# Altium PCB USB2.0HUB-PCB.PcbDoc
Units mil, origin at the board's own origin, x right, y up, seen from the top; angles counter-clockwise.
Board outline 1475 x 1955 mil, 2 copper layers (Top Layer, Bottom Layer); 18 components, 17 nets, 70 pads, 63 vias.
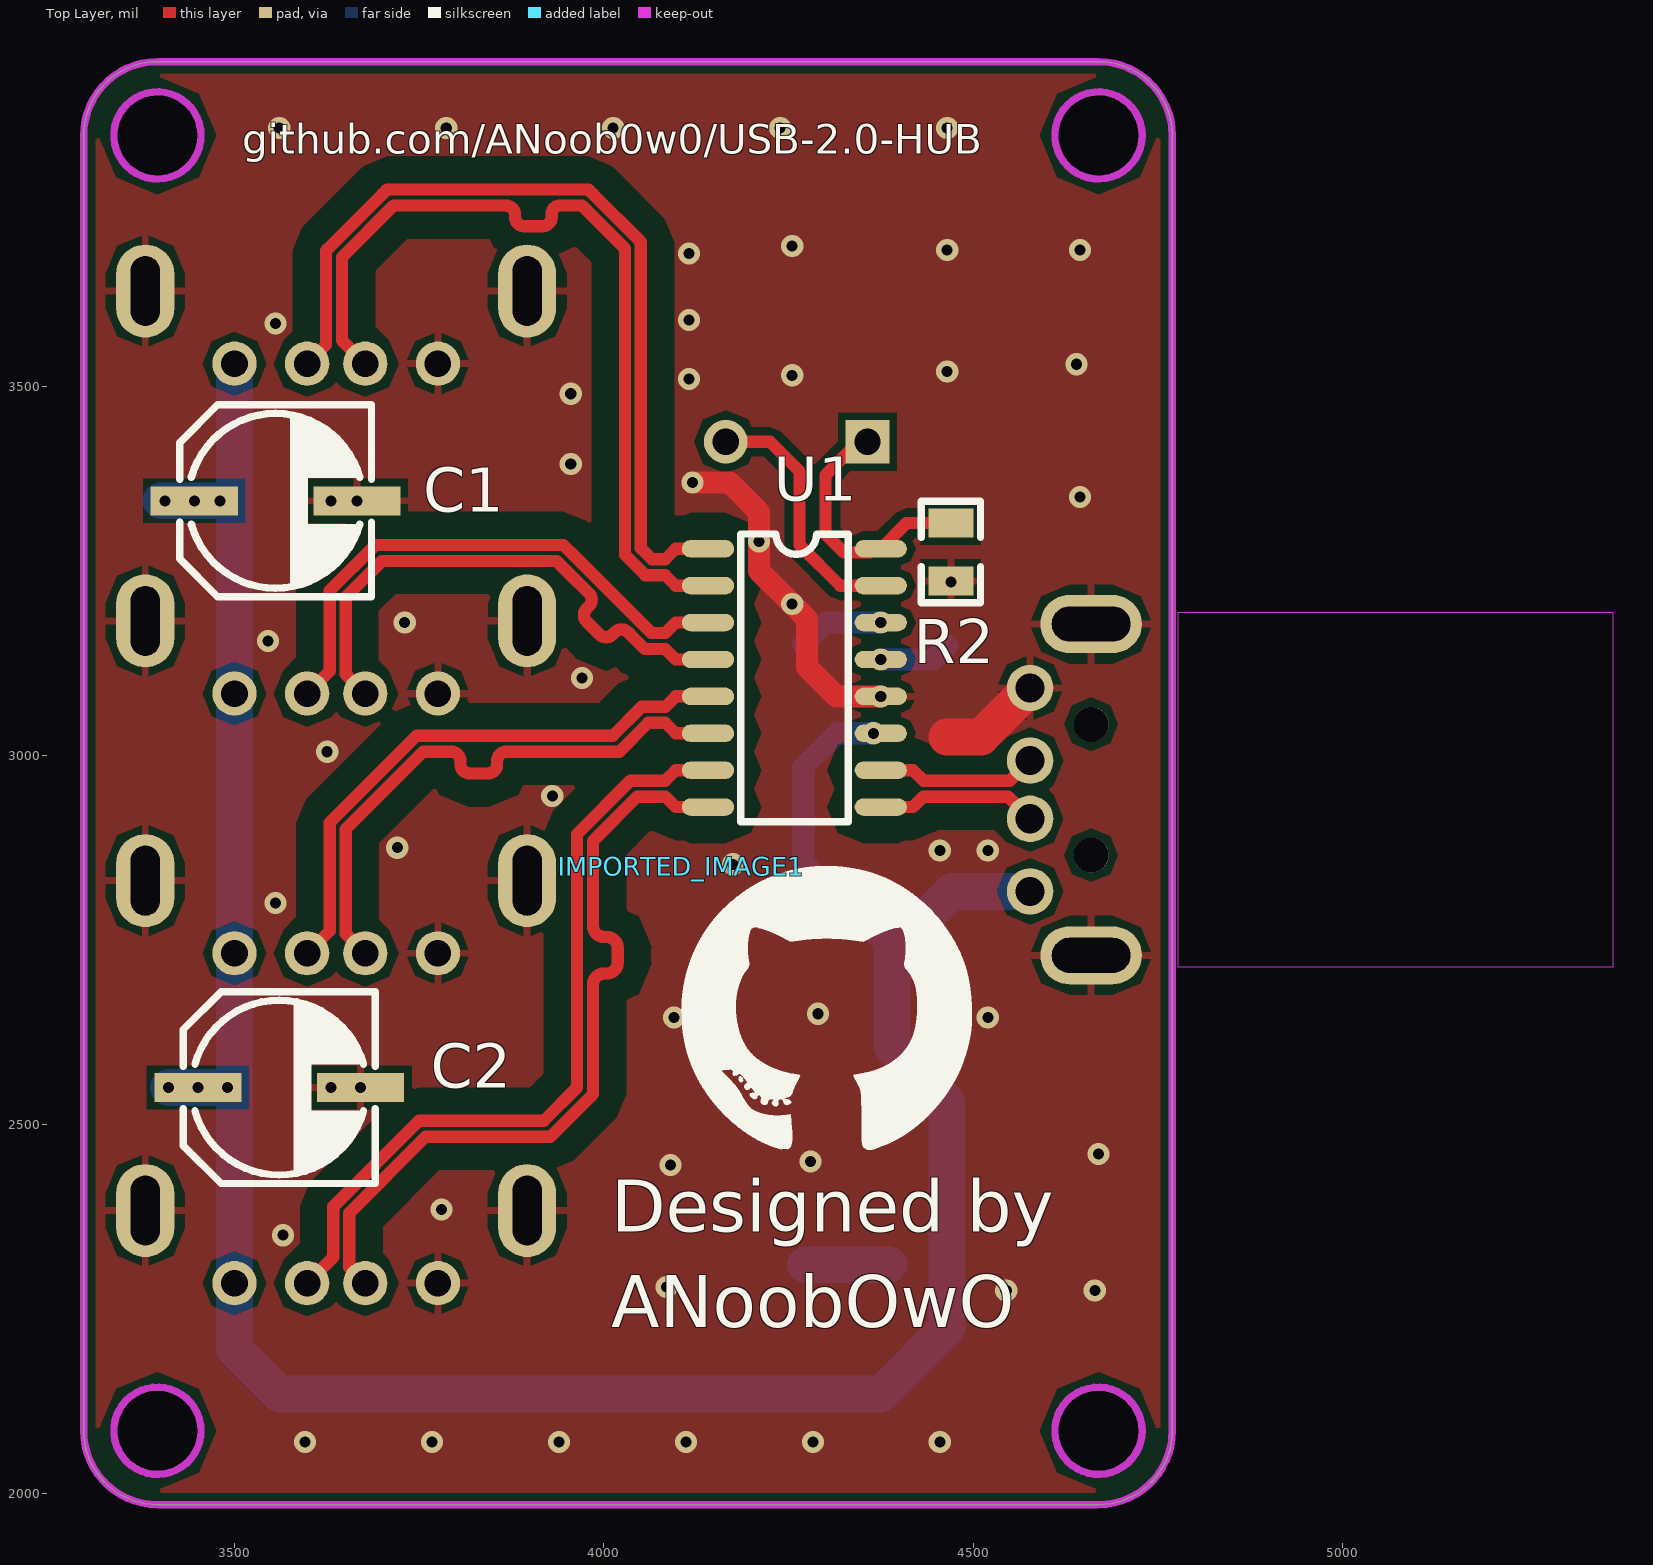
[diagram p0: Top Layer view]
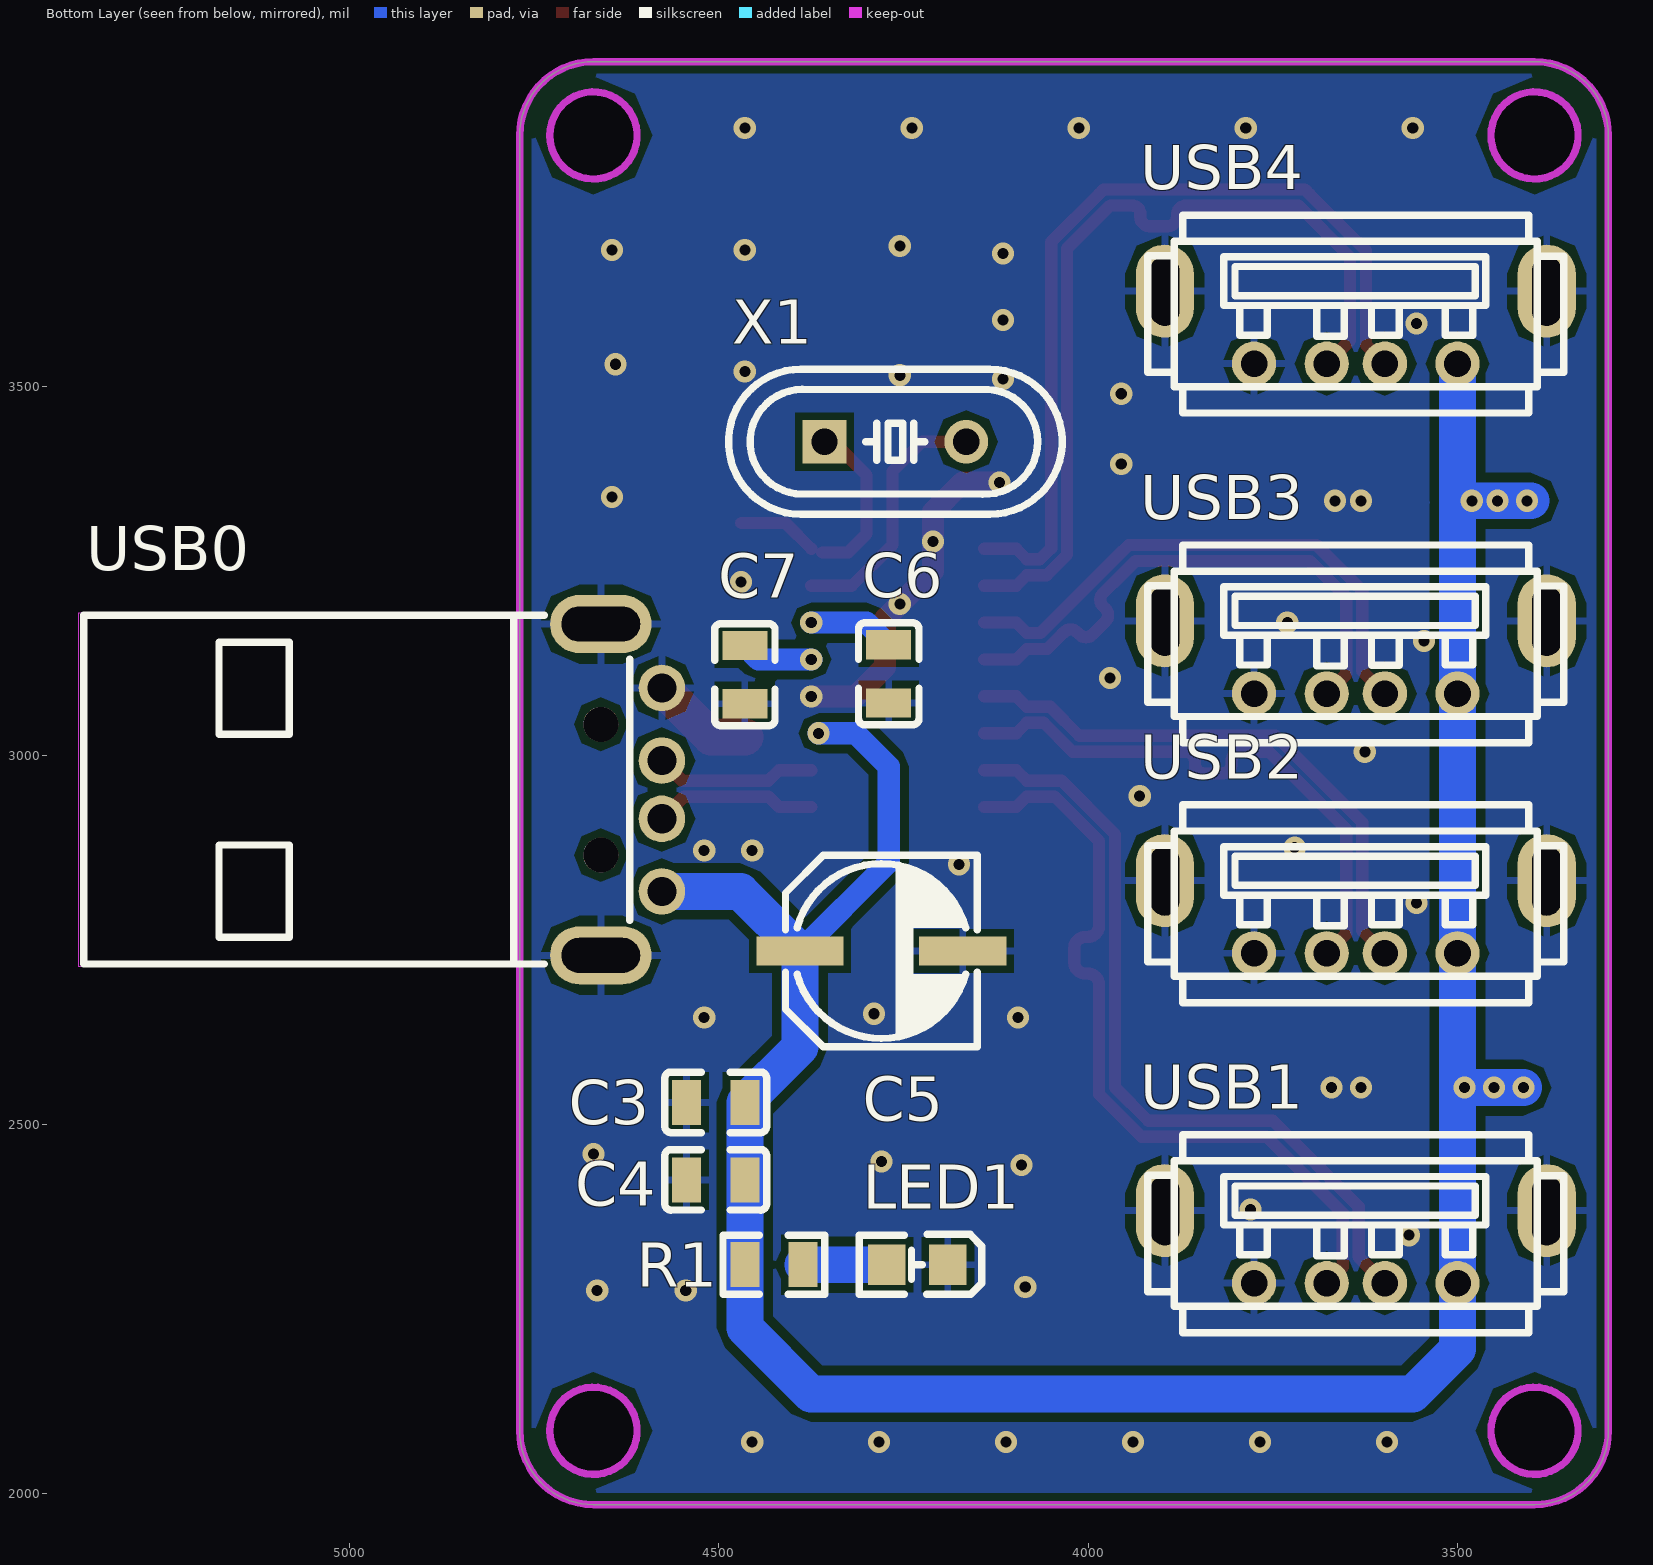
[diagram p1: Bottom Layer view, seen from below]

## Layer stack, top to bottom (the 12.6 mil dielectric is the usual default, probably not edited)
Top Solder: solder mask 0.4, Solder Resist, Dk 3.5
Top Layer: signal copper 1.4
Dielectric 1: dielectric 12.6, FR-4, Dk 4.8
Bottom Layer: signal copper 1.4
Bottom Solder: solder mask 0.4, Solder Resist, Dk 3.5

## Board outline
3295,2085 ccw(c3395,2085) 3395,1985 4670,1985 ccw(c4670,2085) 4770,2085 4770,3840 ccw(c4670,3840) 4670,3940 3395,3940 ccw(c3395,3840) 3295,3840
cut-out: 4610.94,3840 ccw(c4670,3840) 4670,3780.94 ccw(c4670,3840) 4729.06,3840 ccw(c4670,3840) 4670,3899.06 ccw(c4670,3840)
cut-out: 4610.94,2085 ccw(c4670,2085) 4670,2025.94 ccw(c4670,2085) 4729.06,2085 ccw(c4670,2085) 4670,2144.06 ccw(c4670,2085)
cut-out: 3335.94,2085 cw(c3395,2085) 3395,2144.06 cw(c3395,2085) 3454.06,2085 cw(c3395,2085) 3395,2025.94 cw(c3395,2085)
cut-out: 3395,3780.94 cw(c3395,3840) 3335.94,3840 cw(c3395,3840) 3395,3899.06 cw(c3395,3840) 3454.06,3840 cw(c3395,3840)
cut-out: 3450,3855

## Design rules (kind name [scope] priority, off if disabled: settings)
Clearance Clearance_polygon_top [InPolygon vs InNetClass('signal')  And OnTopLayer] p1: gap=33.28 ignorepadtopadclearanceinfootprint=FALSE
Clearance Clearance_polygon [InPolygon] p2: gap=10 ignorepadtopadclearanceinfootprint=FALSE
Clearance [All] p3: gap=5 ignorepadtopadclearanceinfootprint=FALSE
DiffPairsRouting [All] p1: maxlimit=10 minlimit=5 mostfreqgap=5 toplayer_minwidth=10 toplayer_maxwidth=20 toplayer_prefwidth=16.64 bottomlayer_minwidth=10 bottomlayer_maxwidth=20 bottomlayer_prefwidth=16.64 maxuncoupledlength=500
PlaneClearance [All] p1 off: clearance=20
PlaneConnect PlaneConnect_Via [IsVia] p1: planeconnectstyle=Direct reliefexpansion=20 reliefentries=4 reliefconductorwidth=10 reliefairgap=10
PlaneConnect [All] p2: pad.planeconnectstyle=Relief pad.reliefexpansion=20 pad.reliefentries=4 pad.reliefconductorwidth=10 pad.reliefairgap=10 via.planeconnectstyle=Direct via.reliefexpansion=20 via.reliefentries=4 via.reliefconductorwidth=10 via.reliefairgap=10
PolygonConnect PolygonConnect_Via [IsVia] p1: connectstyle=Direct reliefconductorwidth=10 reliefentries=4 polygonreliefangle="90 Angle" airgapwidth=10
PolygonConnect [All] p2: thpad.connectstyle=Relief thpad.reliefconductorwidth=10 thpad.reliefentries=4 thpad.polygonreliefangle="90 Angle" thpad.airgapwidth=10 smdpad.connectstyle=Relief smdpad.reliefconductorwidth=10 smdpad.reliefentries=4 smdpad.polygonreliefangle="90 Angle" smdpad.airgapwidth=10 via.connectstyle=Direct via.reliefconductorwidth=10 via.reliefentries=4 via.polygonreliefangle="90 Angle" via.airgapwidth=10
RoutingVias [All] p1: holewidth=15 width=30 viastyle="Through Hole" minholewidth=12.5 minwidth=25 maxholewidth=28 maxwidth=50
SolderMaskExpansion [All] p1: expansion=4
Width [All] p1: maxlimit=50 minlimit=10 preferedwidth=16.64 minimp=50.000000 maximp=50.000000 favimp=50.000000
27 further rules are at their usual default settings.

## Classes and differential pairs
net class signal: NetU1_1 NetU1_2 NetU1_3 NetU1_4 NetU1_5 NetU1_6 NetU1_7 NetU1_8 NetU1_9 NetU1_10
differential pair class "USB 90OM": NewDifferentialPair1 NewDifferentialPair2 NewDifferentialPair3 NewDifferentialPair4 NewDifferentialPair5
component class USB2.0HUB: C1 C2 C3 C4 C5 C6 C7 LED1 R1 R2 U1 USB0 USB1 USB2 USB3 USB4 X1
differential pair NewDifferentialPair5: +NetU1_10 -NetU1_9
differential pair NewDifferentialPair4: +NetU1_8 -NetU1_7
differential pair NewDifferentialPair3: +NetU1_6 -NetU1_5
differential pair NewDifferentialPair2: +NetU1_4 -NetU1_3
differential pair NewDifferentialPair1: +NetU1_2 -NetU1_1

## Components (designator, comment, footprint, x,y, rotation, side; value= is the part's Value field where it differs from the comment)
C1 "220uF" CAP-SMD_BD6.3-L6.6-W6.6-FD 3555,3345 r0 top
C2 "220uF" CAP-SMD_BD6.3-L6.6-W6.6-FD 3560,2550 r0 top
C3 "1uF" C0805 4504.37,2530 r180 bottom
C4 "10nF" C0805 4504.37,2425 r180 bottom
C5 "220uF" CAP-SMD_BD6.3-L6.6-W6.6-FD 4280,2735 r180 bottom
C6 "10uF" C0805 4270,3110.63 r90 bottom
C7 "10uF" C0805 4465,3109.37 r90 bottom
IMPORTED_IMAGE1 "Comment" IMPORTED_IMAGE 4105,2850 r0 top (schematic designator IMPORTED_IMAGE)
LED1 "ORH-G35A" LED0805-R-RD 4231.35,2310 r0 bottom
R1 "1K" R0805 4425.63,2310 r0 bottom
R2 "0Ω" R0805 4470,3275.63 r90 top
U1 "SL2.1A" SOP-16_L10.0-W3.9-P1.27-LS6.0-BL 4258,3105 r270 top
USB0 "USB-05" USB-A-TH_48037-0001 4618.66,2953.58 r270 bottom
USB1 "A/F180 White plastic13.7" USB-A-TH_USB-M-22 3637.2,2334.2 r0 bottom
USB2 "A/F180 White plastic13.7" USB-A-TH_USB-M-22 3637.2,2781.13 r0 bottom
USB3 "A/F180 White plastic13.7" USB-A-TH_USB-M-22 3637.2,3133.07 r0 bottom
USB4 "A/F180 White plastic13.7" USB-A-TH_USB-M-22 3637.2,3580 r0 bottom
X1 "12MHz" HC-49US_L11.5-W4.5-P4.88 4261,3425 r180 bottom

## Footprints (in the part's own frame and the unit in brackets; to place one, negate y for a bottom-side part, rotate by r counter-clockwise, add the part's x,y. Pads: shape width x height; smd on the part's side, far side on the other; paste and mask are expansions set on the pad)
C0805 [mm]
  rect 1x1.55 smd: 1(-1,0) 2(1,0)
  silkscreen extent -1.75,-1.04 1.75,1.04
CAP-SMD_BD6.3-L6.6-W6.6-FD [mm]
  rect 3x1 smd: 1(-2.8,0) 2(2.8,0)
  silkscreen extent -3.3,-3.3 3.3,3.3
HC-49US_L11.5-W4.5-P4.88 [mm]
  rect 1.5x1.5 hole 0.9: 1(-2.438,0)
  round 1.5 hole 0.9: 2(2.438,0)
  silkscreen extent -5.74,-2.5 5.74,2.5
IMPORTED_IMAGE [mil]
  silkscreen extent 0,-384 393,0
LED0805-R-RD [mil]
  rect 51.2x55.1 smd: 1(41.35,0) 2(-41.35,0)
  silkscreen extent -88,-41 78,40
R0805 [mm]
  rect 1x1.55 smd: 1(-1,0) 2(1,0)
  silkscreen extent -1.75,-1.02 1.75,1.02
SOP-16_L10.0-W3.9-P1.27-LS6.0-BL [mil]
  oval 23.62x70.79 smd: 1(-175,-117) 2(-125,-117) 3(-75,-117) 4(-25,-117) 5(25,-117) 6(75,-117) 7(125,-117) 8(175,-117) 9(175,117) 10(125,117) 11(75,117) 12(25,117) 13(-25,117) 14(-75,117) 15(-125,117) 16(-175,117)
  silkscreen extent -195,-73 195,73
USB-A-TH_48037-0001 [mm]
  round 1.6 hole 1: 1(3.5,1.05) 2(1,1.05) 3(-1,1.05) 4(-3.5,1.05)
  oval 2x3.5 hole 1.2 slot 2.7 at 90 deg: 5(-5.7,-1.05) 6(5.7,-1.05)
  round 1.2 hole 1.2 unplated: ""(-2.25,-1.05) ""(2.25,-1.05)
  Keep-Out Layer board cut-out: -6.096,-4.03 6.096,-4.03 6.096,-19.016 -6.096,-19.016
  silkscreen extent -6,-18.85 6,-0.05
USB-A-TH_USB-M-22 [mil]
  oval 78.74x125.98 hole 39.37 slot 94.49 at 90 deg: 0(-258.66,-49.2) 0(258.66,-49.2)
  round 60 hole 36: 1(-137.8,49.2) 2(-39.4,49.2) 3(39.4,49.2) 4(137.8,49.2)
  silkscreen extent -282,-152 282,116

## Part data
C1 C2 C5: BOM_Manufacturer=ROQANG, BOM_Manufacturer Part=RVT1C221M0607
C3: BOM_Manufacturer=SAMSUNG, BOM_Manufacturer Part=CL21F105ZOFNNNE
C4 C6 C7: library part 1uF, BOM_Manufacturer=SAMSUNG, BOM_Manufacturer Part=CL21F105ZOFNNNE
LED1: BOM_LCSC Assembly=Yes, BOM_Manufacturer=Orient
R1: BOM_Manufacturer=UniOhm, BOM_Manufacturer Part=0805W8J0102T5E
R2: library part 1K, BOM_Manufacturer=UniOhm, BOM_Manufacturer Part=0805W8J0102T5E
U1: BOM_LCSC Assembly=Yes, BOM_Manufacturer=CoreChips
USB0: BOM_Manufacturer=SOFNG
USB1 USB2 USB3 USB4: BOM_Manufacturer=ValuePro
X1: BOM_Manufacturer="Yangxing Tech", BOM_Manufacturer Part=X49SD12MSD2SI

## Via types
v1: diameter 30, hole 15, Top Layer to Bottom Layer, tented both sides, 48 vias
v2: diameter 30, hole 15, Top Layer to Bottom Layer, tented bottom, 15 vias

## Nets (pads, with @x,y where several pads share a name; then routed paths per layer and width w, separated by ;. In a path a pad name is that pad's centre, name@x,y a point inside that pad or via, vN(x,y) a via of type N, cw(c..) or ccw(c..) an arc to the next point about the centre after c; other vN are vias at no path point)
GND: C1.2 C2.2 C3.1 C4.1 C5.2 C6.1 C7.1 LED1.2 R2.1 U1.12 USB0.4 USB0.5 USB0.6 USB1.0 USB1.4 USB2.0 USB2.4 USB3.0 USB3.4 USB4.0 USB4.4 | length 639.5
  Top Layer w30: v1(4120,3370) 4170,3370 4210,3330 v1(4210,3290) 4210,3250 v1(4255,3205) 4275,3185 4275,3120 4315,3080 v2(4375,3080)
  Top Layer w50: USB3.0@3883.13,3195 USB3.0@3895.86,3182.27 ; USB1.0@3895.86,2383.4 USB1.0@3895.86,2405 ; 4465,3025 4510.94,3025 USB0.4
  other v1: 3595,2070 3767,2070 3939,2070 4111,2070 4283,2070 4455,2070 4545,2275 4665,2275 4085,2280 3565,2350 3780,2385 4090,2445 4280,2450 4670,2460 4095,2645 4520,2645 4290,2650 3555,2800 4175,2852.5 4455,2871.25 4520,2871.25 3720,2875 3930,2945 3625,3005 3970,3105 3545,3155 3730,3180 4645,3350 3955,3395 3955,3490 4115,3510 4255,3515 4465,3520 4640,3530 3555,3585 4115,3590 4115,3680 4465,3685 4645,3685 4255,3690 3560,3850 3786.25,3850 4012.5,3850 4238.75,3850 4465,3850
  other v2: 3630,2550 3670.24,2550 4470,3235 3630,3345 3665.24,3345
NetLED1_1: LED1.1 R1.1 | length 113.6
  Bottom Layer w50: LED1.1 R1.1
NetR2_2: R2.2 U1.16 X1.1 | length 335.5
  Top Layer w16.64: X1.1 4345,3425 4300,3380 4300,3300 4325,3275 U1.16@4360,3275 ; U1.16 4410,3315 R2.2
NetU1_1: U1.1 USB4.2 | length 1171.9
  Top Layer w16.64: USB4.2 3623.36,3556.36 3623.36,3683.96 3629.7,3690.3 3699.7,3760.3 3706.04,3766.64 3978.96,3766.64 3985.3,3760.3 4050,3695.6 4050,3280.82 4065,3265.82 4083.11,3265.82 4097.29,3280 U1.1
NetU1_2: U1.2 USB4.3 | length 1173.6
  Top Layer w16.64: USB4.3 3645,3562.4 3645,3675 3715,3745 3805,3745 3829.82,3745 3867.05,3745 cw(c3867.05,3732.59) 3879.46,3732.59 3879.46,3729.55 ccw(c3891.87,3729.55) 3891.87,3717.14 3916.69,3717.14 ccw(c3916.69,3729.55) 3929.1,3729.55 3929.1,3734.1 cw(c3940,3734.1) 3940,3745 3970,3745 4028.36,3686.64 4028.36,3271.86 4056.04,3244.18 4083.11,3244.18 4097.29,3230 U1.2
NetU1_3: U1.3 USB3.2 | length 745.7
  Top Layer w16.64: USB3.2 3628.36,3114.43 3628.36,3223.36 3690.22,3285.22 3944.78,3285.22 3960,3270 4064.18,3165.82 4083.11,3165.82 4097.29,3180 U1.3
NetU1_4: U1.4 USB3.3 | length 745.7
  Top Layer w16.64: USB3.3 3650,3110.47 3650,3214.4 3699.18,3263.58 3765,3263.58 3855,3263.58 3935.82,3263.58 3953.37,3246.03 3979.69,3219.7 cw(c3970.92,3210.93) 3979.69,3202.15 3976.46,3198.91 ccw(c3985.23,3190.14) 3976.46,3181.36 3994.01,3163.81 ccw(c4002.78,3172.59) 4011.56,3163.81 4014.8,3167.05 cw(c4023.57,3158.28) 4032.35,3167.05 4039.7,3159.7 4055.22,3144.18 4083.11,3144.18 4097.29,3130 U1.4
NetU1_5: U1.5 USB2.2 | length 773.2
  Top Layer w16.64: USB2.2 3628.36,2762.49 3628.36,2908.96 3746.04,3026.64 4011.86,3026.64 4051.04,3065.82 4083.11,3065.82 4097.29,3080 U1.5
NetU1_6: U1.6 USB2.3 | length 773.2
  Top Layer w16.64: USB2.3 3650,2758.53 3650,2790 3650,2900 3755,3005 3775,3005 3793.13,3005 cw(c3793.13,2992.59) 3805.54,2992.59 3805.54,2988.01 ccw(c3817.95,2988.01) 3817.95,2975.6 3842.77,2975.6 ccw(c3842.77,2988.01) 3855.18,2988.01 3855.18,2992.59 cw(c3867.59,2992.59) 3867.59,3005 3880,3005 4020.82,3005 4060,3044.18 4083.11,3044.18 4097.29,3030 U1.6
NetU1_7: U1.7 USB1.2 | length 1072.2
  Top Layer w16.64: USB1.2 3633.36,2320.56 3633.36,2388.96 3749.4,2505 3918.36,2505 3963.36,2550 3963.36,2893.14 4036.04,2965.82 4083.11,2965.82 4097.29,2980 U1.7
NetU1_8: U1.8 USB1.3 | length 1072.2
  Top Layer w16.64: USB1.3 3655,2306.6 3655,2380 3758.36,2483.36 3927.32,2483.36 3985,2541.04 3985,2630 3985,2654.82 3985,2689.57 cw(c3999.89,2689.57) 3999.89,2704.46 4003.71,2704.46 ccw(c4003.71,2719.35) 4018.6,2719.35 4018.6,2739.21 ccw(c4003.71,2739.21) 4003.71,2754.1 3999.89,2754.1 cw(c3999.89,2768.99) 3985,2768.99 3985,2775 3985,2884.18 4045,2944.18 4083.11,2944.18 4097.29,2930 U1.8
NetU1_9: U1.9 USB0.2 | length 220.6
  Top Layer w16.64: U1.9 4418.71,2930 4432.89,2944.18 4547.35,2944.18 USB0.2
NetU1_10: U1.10 USB0.3 | length 219.4
  Top Layer w16.64: U1.10 4418.71,2980 4432.89,2965.82 4550.19,2965.82 USB0.3
NetU1_15: U1.15 X1.2 | length 349.4
  Top Layer w16.64: X1.2 4225,3425 4265,3385 4265,3285 4320,3230 U1.15
VDD5: C1.1 C2.1 C3.2 C4.2 C5.1 R1.2 U1.11 USB0.1 USB1.1 USB2.1 USB3.1 USB4.1 | length 3693.5
  Bottom Layer w30: v2(4365,3030) 4315,3030 4270,2985 4270,2855.24 C5.1
  Bottom Layer w50: v2@3400,3345 v2(3480,3345) ; v2(3410,2550) v2(3450,2550) v2(3490,2550) ; 3499.4,3340 USB3.1 USB2.1 USB1.1 3499.4,2195.6 3560,2135 4375.55,2135 4465,2224.45 R1.2 C4.2 C3.2 4390.24,2604.76 C5.1 4471.02,2815.79 USB0.1 ; 3499.4,3345 USB4.1
  other v2: 3405,3345 3445,3345
VDD18: C6.2 U1.14 | length 117.4
  Bottom Layer w30: C6.2 4300,3180 v2(4375,3180)
VDD33: C7.2 U1.13 | length 97.8
  Bottom Layer w30: v2(4375,3130) 4446.26,3130 C7.2
pads on no net: USB0.

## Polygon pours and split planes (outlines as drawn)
GND on Bottom Layer "GND_L02_P090" (solid, remove dead copper, pour order 90): 3225,3995 3245,3975 4890,3975 4890,1890 4855,1855 4830,1880 3240,1880 3240,3985 3235,3990
GND on Bottom Layer "GND_L02_P008" (solid, pour order 8): 5155,2470
GND on Top Layer "GND_L01_P088" (solid, remove dead copper, pour order 88): 3225,4005 3235,3995 4900,3995 4900,1875 4905,1870 4875,1840 3165,1840 3165,3950 3220,4005

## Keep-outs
Keep-Out Layer:
  circle w10: c3395,2085 r59.06
  circle w10: c4670,3840 r59.06
  circle w10: c4670,2085 r59.06
  circle w10: c3395,3840 r59.06
  lines w10: 3295,2085 ccw(c3395,2085) 3395,1985 4670,1985 ccw(c4670,2085) 4770,2085 4770,3840 ccw(c4670,3840) 4670,3940 3395,3940 ccw(c3395,3840) 3295,3840 3295,2085

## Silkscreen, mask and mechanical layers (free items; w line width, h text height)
Top Overlay:
  text "github.com/ANoob0w0/USB-2.0-HUB" at 3510,3815 h40
  text "Designed by" at 4010,2355 h70
  text "ANoobOwO" at 4010,2225 h70

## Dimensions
3395,3940 to 3402.95,3731.98 on Top Overlay
3395,3940 to 3395,1985 on Top Overlay
3295,3840 to 4770,3840 on Top Overlay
